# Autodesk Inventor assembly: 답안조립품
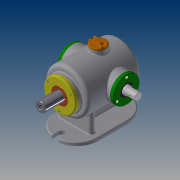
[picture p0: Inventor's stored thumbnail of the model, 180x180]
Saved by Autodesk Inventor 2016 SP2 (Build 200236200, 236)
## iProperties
Created: 2018-02
Part Number: 답안조립품
Document SubType Name: Assembly
Designer: Administrator
Author: Administrator
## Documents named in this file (16)
- D:\380207V1014\답안조립품.iam
- D:\380207V1014\본체.ipt
- D:\380207V1014\가변스프링.ipt
- D:\380207V1014\베어링 6205.ipt
- 베어링 6205.ipt
- D:\380207V1014\본체커버.ipt
- D:\380207V1014\볼트 M4.ipt
- D:\380207V1014\부시.ipt
- D:\380207V1014\상부 캡.ipt
- D:\380207V1014\슬라이드 커버.ipt
- D:\380207V1014\슬라이드.ipt
- D:\380207V1014\오일실.ipt
- 오일실.ipt
- D:\380207V1014\축 커버-1.ipt
- D:\380207V1014\축 커버-2.ipt
- D:\380207V1014\편심축.ipt
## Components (1 placed, 1 different names)
1. 가변스프링:1
